// Mitsubishi GX Works2 project: 顺起逆停（递归）   PLC: FX3U/FX3UC

PROGRAM MAIN
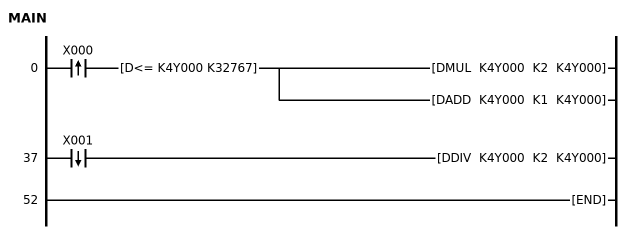
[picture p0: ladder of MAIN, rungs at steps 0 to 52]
0     LDP     X000
      ANDD<=  K4Y000 K32767
      DMUL    K4Y000 K2 K4Y000
      DADD    K4Y000 K1 K4Y000
37    LDF     X001
      DDIV    K4Y000 K2 K4Y000
52    END
END_PROGRAM
